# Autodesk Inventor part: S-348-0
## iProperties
Author: RON CRAIN
Shininess: 85.0
Length Units: 11272
Angle Units: 11286
Time Units: 11279
Mass Units: 11290
Length Display Precision: 3
Angle Display Precision: 2
Compacted: True
PropertySet Name: _Private Model Information
Created: 2001-02
Part Number: S-348-0
Material: Steel, High Strength Low Alloy
Description: NUT, SELF CLINCH, CARBON STEEL, 3-48 UNC
Vendor: PENN MFG. & ENG
Document SubType Name: Modeling
Designer: RON CRAIN
Control State: 0
Master: False
Checked Out: False
PropertySet Name: Design Tracking Control
Density: 0.0
Volumn: 0.0
Area: 0.0
PropertySet Name: Model Information
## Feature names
1. Revolution1
